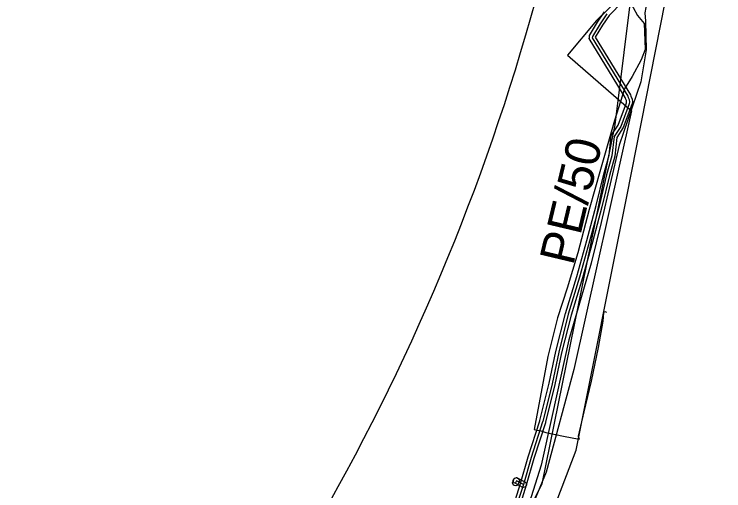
# Model space of a CAD drawing. Extents: x -555222 to -543220, y -1067119 to -1030889.
# Drawn here: x -550846.7 to -550602.6, y -1045023.8 to -1044859.6 of the extents above; entities that cross this region are included whole.
import ezdxf

# ---------------------------------------------------------------- set-up
doc = ezdxf.new("R2010")
doc.units = 0
for name, color, linetype in [('07_ELEKTRO', 7, 'Continuous'), ('07_KANALIZACE', 7, 'Continuous'), ('07_OCH_P A POPISY TI', 7, 'Continuous'), ('07_PLYNOVOD', 7, 'Continuous'), ('07_SDĚLOVACÍ', 7, 'Continuous'), ('07_VODOVOD', 7, 'Continuous')]:
    doc.layers.add(name, color=color, linetype=linetype)

msp = doc.modelspace()

# ---------------------------------------------------------------- linework, layer by layer
at = {"layer": '07_ELEKTRO'}
for points in [[(-550370.08, -1044508.65), (-550574.31, -1044697.39), (-550586.68, -1044732.2), (-550595.61, -1044794.01), (-550611.4, -1044794.01), (-550633.9, -1044847.83), (-550640.01, -1044897.73), (-550665.22, -1045021.34), (-550696.21, -1045084.98), (-550699.72, -1045106.19), (-550748.89, -1045207.29), (-550790.89, -1045276.03), (-550794.79, -1045294.45), (-550820.13, -1045348.15), (-550845.62, -1045384.9), (-550881.8, -1045468.31)], [(-550635.94, -1044922.37), (-550620.97, -1044846.64)], [(-550635.26, -1044854.46), (-550632.25, -1044860.05), (-550629.96, -1044862.8), (-550629.59, -1044871.82), (-550631, -1044875.31), (-550634.15, -1044881.12), (-550636.69, -1044885.34), (-550640.15, -1044896.21), (-550645.01, -1044913.13), (-550648.87, -1044926.87), (-550652.82, -1044941.75), (-550656.48, -1044953.97), (-550659.78, -1044964.21), (-550663.1, -1044977.5), (-550667.83, -1045002.6)], [(-550653.31, -1045009.79), (-550635.94, -1044922.37)], [(-550642.85, -1044962.35), (-550643.43, -1044962.18), (-550643.91, -1044962.38), (-550644.15, -1044965.29), (-550645.77, -1044974.41), (-550648.2, -1044986.06), (-550650.69, -1044996.56), (-550652.64, -1045004.93), (-550652.36, -1045006.03)], [(-550667.83, -1045002.6), (-550665.54, -1045003.16), (-550663.8, -1045003.65), (-550657.72, -1045004.97), (-550652.36, -1045006.03)], [(-550687.32, -1045098.7), (-550653.31, -1045009.79)]]:
    msp.add_lwpolyline(points, dxfattribs=at)
at = {"layer": '07_KANALIZACE'}
msp.add_lwpolyline([(-550615.98, -1044832.05), (-550646.39, -1044861.74), (-550656.29, -1044873.76), (-550634.37, -1044892.85), (-550654.17, -1044981.94), (-550663.64, -1045017.36), (-550687.96, -1045076.3), (-550693.01, -1045094.3), (-550699.89, -1045118.15), (-550714.35, -1045150.94), (-550743.75, -1045198.8), (-550770.63, -1045244.42), (-550789.65, -1045276.35), (-550793.46, -1045294.54), (-550819.11, -1045346.16), (-550837.43, -1045376.6), (-550851.47, -1045402.76)], dxfattribs=at)
at = {"layer": '07_OCH_P A POPISY TI'}
for p, q in [((-550637.41, -1044855.4), (-550642.06, -1044860.06)), ((-550645.97, -1044862.34), (-550643.62, -1044858.8)), ((-550642.06, -1044860.06), (-550644.29, -1044863.42)), ((-550648.77, -1044866.94), (-550645.97, -1044862.34)), ((-550644.29, -1044863.42), (-550646.8, -1044867.55)), ((-550648.85, -1044868.03), (-550648.82, -1044867.62)), ((-550636.49, -1044888.35), (-550648.85, -1044868.03)), ((-550648.82, -1044867.62), (-550648.77, -1044866.94)), ((-550646.8, -1044867.55), (-550634.71, -1044887.43)), ((-550634.71, -1044887.43), (-550634.52, -1044887.87)), ((-550636.37, -1044888.65), (-550636.49, -1044888.35)), ((-550636.06, -1044889.37), (-550636.37, -1044888.65)), ((-550636.1, -1044890.18), (-550636.03, -1044889.77)), ((-550636.03, -1044889.77), (-550636.06, -1044889.37)), ((-550634.52, -1044887.87), (-550634.1, -1044888.89)), ((-550634.01, -1044889.85), (-550634.16, -1044890.7)), ((-550634.1, -1044888.89), (-550634.01, -1044889.85)), ((-550638.94, -1044897.79), (-550636.1, -1044890.18)), ((-550634.16, -1044890.7), (-550637.14, -1044898.69)), ((-550641.27, -1044901.34), (-550638.94, -1044897.79)), ((-550637.14, -1044898.69), (-550639.33, -1044902.04)), ((-550642.05, -1044908.15), (-550641.27, -1044901.34)), ((-550639.33, -1044902.04), (-550640.09, -1044908.53)), ((-550643.89, -1044914.69), (-550642.05, -1044908.15)), ((-550640.09, -1044908.53), (-550641.95, -1044915.19)), ((-550646.46, -1044925.48), (-550643.89, -1044914.69)), ((-550641.95, -1044915.19), (-550644.52, -1044925.98)), ((-550649.68, -1044937.58), (-550646.46, -1044925.48)), ((-550644.52, -1044925.98), (-550647.76, -1044938.1)), ((-550653.16, -1044949.9), (-550649.68, -1044937.58)), ((-550647.76, -1044938.1), (-550651.24, -1044950.46)), ((-550657.02, -1044962.7), (-550653.16, -1044949.9)), ((-550651.24, -1044950.46), (-550655.1, -1044963.24)), ((-550660.31, -1044975.84), (-550657.02, -1044962.7)), ((-550655.1, -1044963.24), (-550658.37, -1044976.3)), ((-550662.62, -1044986.71), (-550660.31, -1044975.84)), ((-550658.37, -1044976.3), (-550660.68, -1044987.15)), ((-550665.82, -1044999.61), (-550662.62, -1044986.71)), ((-550660.68, -1044987.15), (-550663.9, -1045000.17)), ((-550669.85, -1045012.06), (-550665.85, -1044999.69)), ((-550665.85, -1044999.69), (-550665.82, -1044999.61)), ((-550663.94, -1045000.31), (-550667.93, -1045012.64)), ((-550663.9, -1045000.17), (-550663.94, -1045000.31)), ((-550672.48, -1045021.3), (-550669.85, -1045012.06)), ((-550667.93, -1045012.64), (-550670.56, -1045021.88)), ((-550674.85, -1045019.95), (-550674.7, -1045019.56)), ((-550674.8, -1045019.84), (-550674.61, -1045019.47)), ((-550674.7, -1045019.56), (-550673.94, -1045019.23)), ((-550674.61, -1045019.47), (-550673.82, -1045019.23)), ((-550673.94, -1045019.23), (-550673.56, -1045019.38)), ((-550673.82, -1045019.23), (-550673.45, -1045019.43)), ((-550673.56, -1045019.38), (-550673.17, -1045019.53)), ((-550673.45, -1045019.43), (-550671.05, -1045020.71)), ((-550673.17, -1045019.53), (-550672.84, -1045020.29)), ((-550675.28, -1045021.05), (-550675.13, -1045020.67)), ((-550674.95, -1045021.81), (-550675.28, -1045021.05)), ((-550675.13, -1045020.67), (-550674.85, -1045019.95)), ((-550675, -1045020.2), (-550674.8, -1045019.84)), ((-550674.76, -1045021), (-550675, -1045020.2)), ((-550674.56, -1045021.96), (-550674.95, -1045021.81)), ((-550674.39, -1045021.19), (-550674.76, -1045021)), ((-550674.18, -1045022.11), (-550674.56, -1045021.96)), ((-550671.99, -1045022.47), (-550674.39, -1045021.19)), ((-550674.33, -1045027.13), (-550672.48, -1045021.3)), ((-550673.42, -1045021.78), (-550674.18, -1045022.11)), ((-550673.27, -1045021.39), (-550673.42, -1045021.78)), ((-550672.99, -1045020.67), (-550673.27, -1045021.39)), ((-550672.84, -1045020.29), (-550672.99, -1045020.67)), ((-550670.56, -1045021.88), (-550672.43, -1045027.77)), ((-550671.05, -1045020.71), (-550670.68, -1045020.9)), ((-550670.68, -1045020.9), (-550670.44, -1045021.7)), ((-550670.44, -1045021.7), (-550670.64, -1045022.06)), ((-550671.62, -1045022.67), (-550671.99, -1045022.47)), ((-550670.83, -1045022.43), (-550671.62, -1045022.67)), ((-550670.64, -1045022.06), (-550670.83, -1045022.43))]:
    msp.add_line(p, q, dxfattribs=at)
at = {"layer": '07_PLYNOVOD'}
for points in [[(-550642.84, -1044859.43), (-550645.13, -1044862.88), (-550647.79, -1044867.25), (-550647.82, -1044867.7), (-550647.83, -1044867.79), (-550635.6, -1044887.89), (-550635.44, -1044888.26), (-550635.12, -1044889.04), (-550635.08, -1044889.13), (-550635.02, -1044889.81), (-550635.13, -1044890.44), (-550638.04, -1044898.24), (-550640.3, -1044901.69), (-550641.07, -1044908.34), (-550642.92, -1044914.94), (-550645.49, -1044925.73), (-550648.72, -1044937.84), (-550652.2, -1044950.18), (-550656.06, -1044962.97), (-550659.34, -1044976.07), (-550661.65, -1044986.93), (-550664.86, -1044999.89), (-550664.9, -1045000), (-550668.89, -1045012.35), (-550671.52, -1045021.59), (-550673.38, -1045027.45)], [(-550673.92, -1045020.31), (-550674.2, -1045021.03)], [(-550671.52, -1045021.59), (-550673.92, -1045020.31)]]:
    msp.add_lwpolyline(points, dxfattribs=at)
at = {"layer": '07_SDĚLOVACÍ'}
for points in [[(-550607.43, -1044807.45), (-550609.21, -1044816.64), (-550610.26, -1044821.66), (-550615.45, -1044820.33), (-550617.77, -1044826.13), (-550627.52, -1044846.84), (-550628.73, -1044853.46), (-550629.75, -1044859.15), (-550629.55, -1044862.04), (-550629.29, -1044871.93), (-550631.15, -1044882.94), (-550638.57, -1044904.71), (-550644.71, -1044931.31), (-550648.2, -1044945.38), (-550655.92, -1044971.78), (-550661.57, -1044997.8), (-550665.39, -1045014.91), (-550668.89, -1045025.88), (-550674.47, -1045038.53), (-550686.64, -1045061.5), (-550690.84, -1045071.86), (-550693.8, -1045086.14), (-550695.83, -1045095.53)], [(-550629.55, -1044862.04), (-550629.29, -1044871.93)]]:
    msp.add_lwpolyline(points, dxfattribs=at)
at = {"layer": '07_VODOVOD'}
msp.add_arc((-551405.48, -1044653.04), 765.24, 322.68586, 352.70968, dxfattribs=at)

# ---------------------------------------------------------------- texts
at = {"layer": '07_OCH_P A POPISY TI'}
msp.add_text('PE/50', height=12, rotation=76.6027, dxfattribs=at).set_placement((-550654.41, -1044946.47))

doc.saveas('drawing.dxf')
